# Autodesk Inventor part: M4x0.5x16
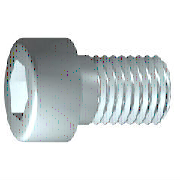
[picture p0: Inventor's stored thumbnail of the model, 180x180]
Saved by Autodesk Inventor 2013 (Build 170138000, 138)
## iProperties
Created: 2014-07
Part Number: M4x0.5x16
Material: Steel, Mild
Description: 6각머리 태핑 나사
Document SubType Name: Modeling
Standard: KS B 1003
Designer: KYOUNG IL JANG
Standards Organization: KS
Language: ko-KR
Size Designation: M 4 x 16
Categories: <MemberInstance><Categories><Category DisplayName="조임쇠" InternalName="e4da775c-781d-43d5-af7c-5136215cf5a6" Mnemonic="FSTN"><Category DisplayName="볼트" InternalN
Density: 1 g/cm^3
Company: 한국ATC센터
IsCustomPart: 1
Author: KYOUNG IL JANG
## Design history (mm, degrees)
revolve "본체" stored, may be unused: angle "d10" = 90 deg
sketch "스케치2"
  geometry: L1 (0, -4.9)-(0, 4.9) reference; L2 (-4.9, 0)-(4.9, 0) reference; L3 (1.732, 0)-(0.866, -1.5); L4 (0.866, -1.5)-(-0.866, -1.5); L5 (-0.866, -1.5)-(-1.732, 0); L6 (-1.732, 0)-(-0.866, 1.5); L7 (-0.866, 1.5)-(0.866, 1.5); L8 (0.866, 1.5)-(1.732, 0); 2 further points
  constraints: 12 end point, 1 coincident, 1 horizontal alignment, 1 point on line, 12 other
extrude "슬롯" join sketch "스케치2" stored distance "d11" = 10; taper "d12" = 0 deg
workplane "Work Plane1"
fillet "Fillet2" dims "d30" = 0.1 (= R)
body "Solid1"
fillet "모깎기1" dims "d17" = 0.4 (= RR)
feature "스레드" dims "d13" = 14.25 (= GEL), "d14" = 0
chamfer "모따기1" distance "d15" = 0.42941 (= -0.5 x SPD + 0.5 x GD); stored, may be unused: second distance "d16" = 0.42941 (= GUL), angle "d27" = 45 deg
sketch "스케치1"
  geometry: L1 (-1, 0)-(16, 0); L2 (16, 0)-(16, 2); L3 (16, 2)-(1.75, 2); L4 (1.75, 2)-(1.32, 2); L5 (1.32, 2)-(0, 2); L6 (0, 2)-(0, 3.5); L7 (0, 3.5)-(-4, 3.5); L8 (-4, 3.5)-(-4, 1.732); L9 (-4, 1.732)-(-2, 1.732); L10 (-2, 1.732)-(-1, 0); L11 (-8, 0)-(20, 0) reference; L12 (0, -0.7)-(0, 4.2) reference; L13 (1.75, 2)-(0, 2)
  constraints: 22 end point, 6 parallel, 2 collinear, 2 perpendicular, 1 horizontal, 1 point on line
  dimensions: "d1" = 14.25 distance from line of L3.end L2 (= GEL); "d2" = 0.42952 distance of L4.end L3.end (computed from GAL); "d3" = 4 distance between parallel lines of L8 L6 (= KOH); "d4" = 2 distance of L8.end L9.end (= INTI); "d5" = 60 deg angle of L10 L1; "d6" = 4 diameter of L3 L1 (= GD); "d7" = 4 diameter of L5 L1 (= BDM); "d8" = 3.4641 diameter of L9 L1 (= 1.1547 x SW); "d9" = 7 diameter of L7 L1 (= KOD); "d26" = 16 distance between parallel lines of L12 L2 (= NLG)
other parameters: "GD" = 4 (= NND) [user parameter; used in 2 equation terms], "NLG" = 16 [user parameter; used in 1 equation term], "GEL" = 14.25 [user parameter; used in 2 equation terms], "KOD" = 7 [user parameter; used in 1 equation term], "KOH" = 4 [user parameter; used in 1 equation term], "INTI" = 2 [user parameter; used in 1 equation term], "GAL" = 0.42941 (= 0.61345 x PTC) [user parameter; used in 1 equation term], "GUL" = 0.42941 (= 0.61345 x PTC) [user parameter; used in 1 equation term], "BDM" = 4 (= NND) [user parameter; used in 1 equation term], "SW" = 3 [user parameter; used in 2 equation terms], "RR" = 0.4 [user parameter; used in 1 equation term], "SPD" = 3.14117 (= NND - 1.2269 x PTC) [user parameter; used in 1 equation term], "d19" = 0, "d28" = 0, "d29" = 0, "R" = 0.1 [user parameter; used in 1 equation term], "PHH" = 0.2 [user parameter], "GD1" = 3.14117 (= THREADDIA - 1.2269 x PTC) [user parameter], "THREADDIA" = 4 [user parameter; used in 1 equation term], "FAWI" = 45 deg [user parameter], "TPU" = 14.28571 (computed from PTC) [user parameter], "PTC" = 0.7 [user parameter; used in 5 equation terms], "NND" = 4 [user parameter; used in 3 equation terms], "TOA" = 30 deg [user parameter], "E0" = 3.465 (= 1.155 x SW) [user parameter]
